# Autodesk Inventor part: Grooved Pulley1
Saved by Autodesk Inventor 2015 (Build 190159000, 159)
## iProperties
Created: 2015-03
Part Number: Grooved Pulley1
Material: Steel
Document SubType Name: Modeling
Designer: Uglješa
Density: 1 g/cm^3
Appearance: Steel
CustomPartVersion: 1
Author: Uglješa
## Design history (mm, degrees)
sketch "Main Sketch"
  geometry: L1 (0, 76)-(42, 76); L2 (42, 76)-(42, 12.861); L3 (42, 12.861)-(31, 9.498); L4 (31, 9.498)-(31, 6.502); L5 (31, 6.502)-(42, 3.139); L6 (42, 3.139)-(42, 0); L7 (42, 0)-(0, 0); L8 (40, 12.25)-(40, 3.75); L9 (31, 8)-(40, 8); L10 (42, 12.861)-(42, 3.139); L11 (0, -4)-(0, 24) reference; L12 (0, 0)-(0, 76)
  constraints: 22 end point, 5 perpendicular, 2 collinear, 2 midpoint, 2 point on line, 1 parallel
  dimensions: "d0" = 8.5 distance of L8.start L8.end (= da_Bw); "d1" = 34 deg angle of L3 L5 (= da_Alfa); "d2" = 2 distance between parallel lines of L2 L8 (= da_c); "d6" = 76 distance between parallel lines of L7 L1 (computed from d5, da_ng, da_Sg); "d21" = 80 diameter of L8 L11 (= da_Dw); "d25" = 11 distance between parallel lines of L4 L10 (= da_Hd); "d27" = 8 distance between parallel lines of L7 L9 (= da_Se)
node "Belt Plane"
revolve "Body" stored, may be unused: angle "d7" = 90 deg
revolve "Groove" stored, may be unused: angle "d15" = 90 deg
fillet "Fillet External" dims "d8" = 0 (computed from da_r1), "d10" = 0, "da_r1" = 0 [user parameter; used in 1 equation term]
fillet "Fillet Internal" dims "d9" = 0 (computed from da_r2), "d11" = 0, "da_r2" = 0 [user parameter; used in 1 equation term]
pattern_linear "Groove Pattern" dims "d18" = 12 (= da_Sg)
body "Solid1"
other parameters: "d5" = 8 (= da_Se), "da_Bw" = 8.5 [user parameter; used in 1 equation term], "da_Alfa" = 34 deg [user parameter; used in 1 equation term], "da_c" = 2 [user parameter; used in 1 equation term], "da_Dw" = 80 [user parameter; used in 1 equation term], "da_Hd" = 11 [user parameter; used in 1 equation term], "da_Se" = 8 [user parameter; used in 2 equation terms], "da_Sg" = 12 [user parameter; used in 2 equation terms], "d24" = 0, "d26" = 0
